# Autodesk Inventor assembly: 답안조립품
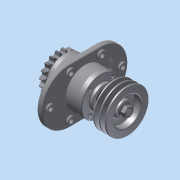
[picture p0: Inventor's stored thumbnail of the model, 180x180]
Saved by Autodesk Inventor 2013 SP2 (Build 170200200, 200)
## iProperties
Created: 2015-02
Part Number: 답안조립품
Document SubType Name: Assembly
Designer: dgall
Author: dgall
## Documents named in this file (12)
- C:\Documents and Settings\dgall\바탕 화면\450207V1020\답안조립품.iam
- C:\Documents and Settings\dgall\바탕 화면\450207V1020\본체.ipt
- C:\Documents and Settings\dgall\바탕 화면\450207V1020\2-커버.ipt
- C:\Documents and Settings\dgall\바탕 화면\450207V1020\3-축.ipt
- C:\Documents and Settings\dgall\바탕 화면\450207V1020\6-베어링 6206.ipt
- C:\Documents and Settings\dgall\바탕 화면\450207V1020\7-부시.ipt
- C:\Documents and Settings\dgall\바탕 화면\450207V1020\8-오일실 30x42.ipt
- C:\Documents and Settings\dgall\바탕 화면\450207V1020\11-키 6x6.ipt
- C:\Documents and Settings\dgall\바탕 화면\450207V1020\4-V벨트풀리.ipt
- C:\Documents and Settings\dgall\바탕 화면\450207V1020\5-체인 스프로킷.ipt
- C:\Documents and Settings\dgall\바탕 화면\450207V1020\9-M16-너트.ipt
- C:\Documents and Settings\dgall\바탕 화면\450207V1020\10-M6.ipt
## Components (22 placed, 10 different names)
1. 2-커버:1
2. 3-축:1
3. 6-베어링 6206:1
4. 6-베어링 6206:2
5. 7-부시:1
6. 2-커버:2
7. 8-8-오일실 30x42:1
8. 8-8-오일실 30x42:2
9. 11-키 6x6:1
10. 11-키 6x6:2
11. 4-V벨트풀리:1
12. 5-체인 스프로킷:1
13. 9-M16 너트:1
14. 9-M16 너트:2
15. 10-M6:1
16. 10-M6:2
17. 10-M6:3
18. 10-M6:4
19. 10-M6:5
20. 10-M6:6
21. 10-M6:7
22. 10-M6:8
